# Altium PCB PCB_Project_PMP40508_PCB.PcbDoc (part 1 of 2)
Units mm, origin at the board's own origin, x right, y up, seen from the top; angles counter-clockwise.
Board outline 120 x 67 mm, 2 copper layers (Top Layer, Bottom Layer), stack 1.575 mm thick; 78 components, 43 nets, 177 pads, 0 vias.
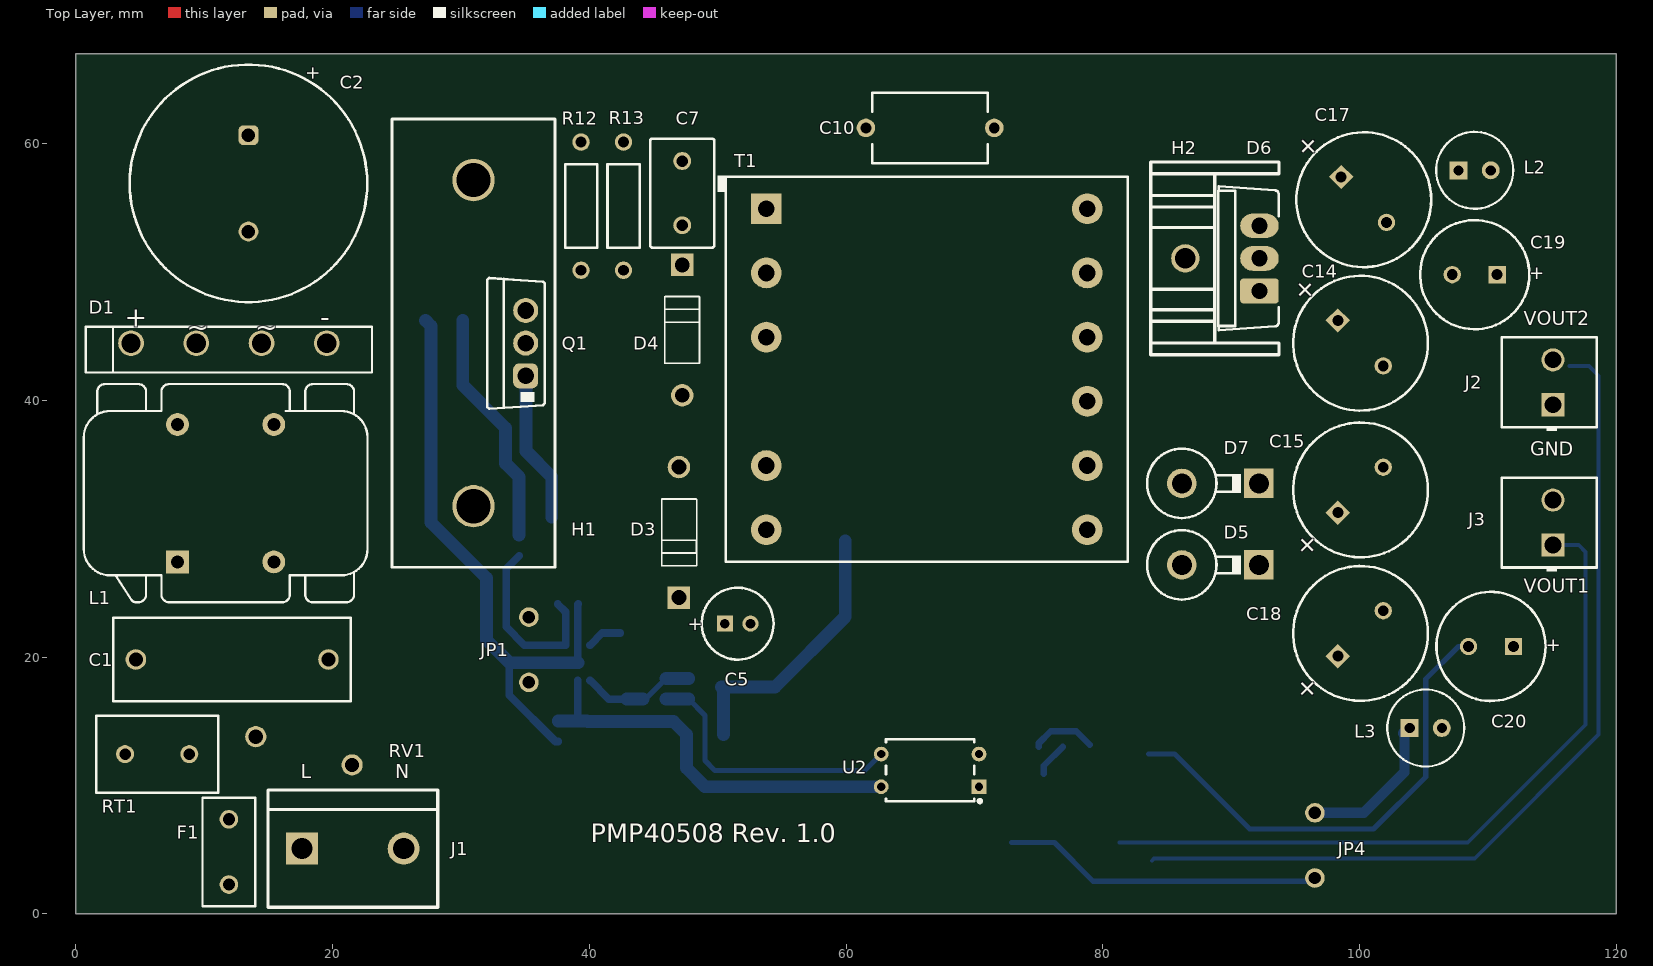
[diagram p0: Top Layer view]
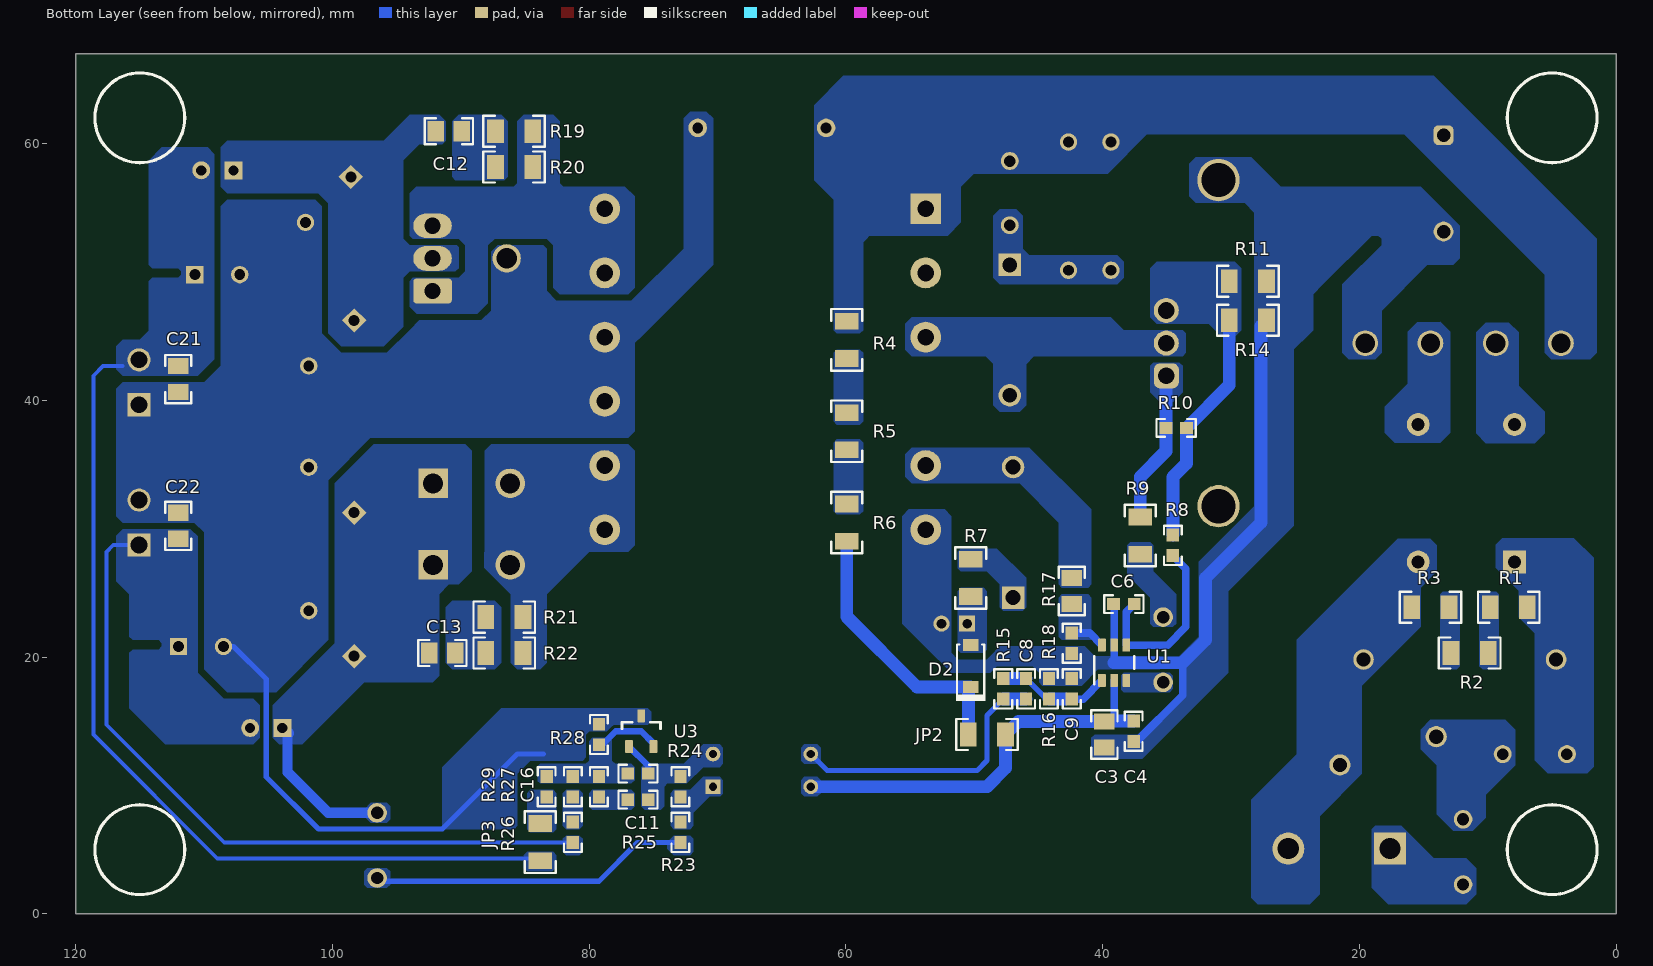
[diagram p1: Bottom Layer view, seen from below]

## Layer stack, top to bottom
Top Solder: solder mask 0.0102, Solder Resist, Dk 3.5
Top Layer: signal copper 0.0356
Dielectric1: core 1.5037, FR-4, Dk 4.8
Bottom Layer: signal copper 0.0356
Bottom Solder: solder mask 0.0102, Solder Resist, Dk 3.5

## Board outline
0,0 0,67 120,67 120,0

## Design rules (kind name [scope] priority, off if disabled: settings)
AcuteAngle [All] p1: minimum=4.50000000000000E+0001 checktracksonly=FALSE
AssemblyTestPointUsage [All] p1: valid=2
Clearance Clearance_BoardEdge_MountingHoles [OnCopper and InComponentClass('Mounting Holes') vs IsKeepOut] p1: gap=1.016 ignorepadtopadclearanceinfootprint=FALSE except(0: Arc-Hole Track-Hole SMDPad-Hole THPad-Hole Via-Hole Fill-Hole Poly-Hole Region-Hole Text-Hole)
Clearance Clearance_BoardEdge_Poly [OnCopper and InPoly vs IsKeepOut] p2: gap=0.635 ignorepadtopadclearanceinfootprint=FALSE except(0: Arc-Hole Track-Hole SMDPad-Hole THPad-Hole Via-Hole Fill-Hole Poly-Hole Region-Hole Text-Hole)
Clearance Clearance_BoardEdge [OnCopper and Not InComponentClass('Logo') and not InComponentClass('FiducialMark') and not InRegion(1000,500,4000,800) and Not IsKeepout vs IsKeepOut] p3: gap=0.2 ignorepadtopadclearanceinfootprint=FALSE
Clearance Clearance_Poly [InPolygon] p4: gap=0.254 ignorepadtopadclearanceinfootprint=FALSE
Clearance [All] p5: gap=0.2 ignorepadtopadclearanceinfootprint=FALSE
ComponentClearance ComponentClearance_Logo [All] p1: gap=0.254 collisioncheckmode=3 verticalgap=0.254 showdistances=TRUE
ComponentClearance ComponentClearance_ScrewToNut [(HasFootprint('NY PMS 440 0025 PH')) vs (HasFootprint('Keystone_1902C'))] p2: gap=0.127 collisioncheckmode=3 verticalgap=0.254 showdistances=FALSE
ComponentClearance ComponentClearance_MountingHoles [InComponentClass('Mounting Holes')] p3: gap=0.254 collisioncheckmode=3 verticalgap=2540 showdistances=FALSE
ComponentClearance ComponentClearance_SmallPassives [HasFootprint('0201*') or HasFootprint('0402*') or HasFootprint('0508') or HasFootprint('0603*') or HasFootprint('0612') or HasFootprint('0805*') or HasFootprint('0815*') or HasFootprint('0830*') or HasFootprint('1206*') or HasFootprint('1210*') or HasFootprint('1808*') or HasFootprint('1812*') or HasFootprint('1825*') or HasFootprint('2010*') or HasFootprint('2220*') or HasFootprint('2225*') or HasFootprint('2512*') or HasFootprint('2728*') or HasFootprint('3518*') vs HasFootprint('0201*') or HasFootprint('0402*') or HasFootprint('0508') or HasFootprint('0603*') or HasFootprint('0612') or HasFootprint('0805*') or HasFootprint('0815*') or HasFootprint('0830*') or HasFootprint('1206*') or HasFootprint('1210*') or HasFootprint('1808*') or HasFootprint('1812*') or HasFootprint('1825*') or HasFootprint('2010*') or HasFootprint('2220*') or HasFootprint('2225*') or HasFootprint('2512*') or HasFootprint('2728*') or HasFootprint('3518*')] p4: gap=0.254 collisioncheckmode=3 verticalgap=0.254 showdistances=FALSE
ComponentClearance ComponentClearance_THtoSMT [IsThruComponent vs IsSMTComponent] p5: gap=0.254 collisioncheckmode=3 verticalgap=2540 showdistances=FALSE
ComponentClearance ComponentClearance_THtoTH [IsThruComponent vs IsThruComponent] p6: gap=0.254 collisioncheckmode=3 verticalgap=2540 showdistances=FALSE
ComponentClearance [All] p7: gap=0.254 collisioncheckmode=3 verticalgap=0.254 showdistances=FALSE
DiffPairsRouting [All] p1: maxlimit=2.54 minlimit=0.254 mostfreqgap=0.254 toplayer_minwidth=0.381 toplayer_maxwidth=0.381 toplayer_prefwidth=0.381 bottomlayer_minwidth=0.381 bottomlayer_maxwidth=0.381 bottomlayer_prefwidth=0.381 maxuncoupledlength=25.4
FabricationTestPointUsage TestPointUsage [All] p1: valid=2 allowmultiple=FALSE
FabricationTestpoint Testpoint [All] p1: side=3 testpointundercomponent=TRUE minsize=1.016 maxsize=2.54 preferedsize=1.524 minholesize=0 maxholesize=1.016 preferedholesize=0.813 testpointgrid=0.025 allowsidetop=TRUE allowsidebottom=TRUE usegrid=TRUE gridtolerance=0
FanoutControl Fanout_LCC [IsLCC] p1: bgadir=Out bgaviamode=Centered fanoutstyle=Auto fanoutdirection=Alternating viagrid=0.025 // Fanout_LCC (Default Rule)
FanoutControl Fanout_BGA [IsBGA] p2: bgadir=Out bgaviamode=Centered fanoutstyle=Auto fanoutdirection=Alternating viagrid=0.025 // Fanout_BGA (Default Rule)
FanoutControl Fanout_Default [All] p4: bgadir=Out bgaviamode=Centered fanoutstyle=Auto fanoutdirection=Alternating viagrid=0.025 // Fanout_Default (Default Rule)
FanoutControl Fanout_Small [(CompPinCount < 5)] p5: bgadir=Out bgaviamode=Centered fanoutstyle=Auto fanoutdirection=OutThenIn viagrid=0.025 // Fanout_Small (Default Rule)
Height [All] p1: minheight=0 maxheight=40 prefheight=12.7
HoleSize [All] p1: absolutevalues=TRUE maxlimit=6.375 minlimit=0.152 maxpercent=80.000 minpercent=20.000
MinimumAnnularRing [All] p1: minimumring=0.1
MinimumSolderMaskSliver MinimumSolderMaskSliver_Logo [InComponentClass('Logo') vs InComponentClass('Logo')] p1: minsoldermaskwidth=0.018
MinimumSolderMaskSliver [All] p2: minsoldermaskwidth=0
PlaneConnect [All] p1: planeconnectstyle=Direct reliefexpansion=0.254 reliefentries=4 reliefconductorwidth=0.254 reliefairgap=0.254
PolygonConnect [All] p1: connectstyle=Direct reliefconductorwidth=0.254 reliefentries=4 polygonreliefangle="90 Angle" airgapwidth=0.254
RoutingCorners [All] p1: cornerstyle=45-Degree minsetback=0.254 maxsetback=2.54
RoutingVias [All] p1: holewidth=0.406 width=0.864 viastyle="Through Hole" minholewidth=0.203 minwidth=0.406 maxholewidth=1.016 maxwidth=1.651
SMDToCorner [All] p1: distance=0
SilkToBoardRegionClearance [Not ((IsComment or IsDesignator) And (Hide <> 'False')) and not InRegion(1000,500,4000,800)] p1:
SilkToSilkClearance [All] p1: silktosilkclearance=0
SilkToSolderMaskClearance SilkscreenOverComponentPads [IsPad] p1: minsilkscreentomaskgap=0 clearancetoexposedcopper=TRUE
SolderMaskExpansion [All] p1: expansion=0.076
Width [All] p1: maxlimit=2.54 minlimit=0.152 preferedwidth=0.254 checkconnectedcopper=TRUE
13 further rules are at their usual default settings.

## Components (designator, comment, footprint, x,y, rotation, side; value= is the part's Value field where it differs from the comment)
C1 "890324025027CS" WCAP-FTX2_1800x600x1150 12.192,19.812 r180 top value=0.22uF
C2 "EKXG401ELL101MMN3S" Chemi-Con_1800x3150 13.462,56.896 r270 top value=100uF
C3 "C2012X7R1H225K125AC" 0805_HV 39.878,13.97 r270 bottom value=2.2uF
C4 "GRM188R71H103KA01D" 0603 37.592,14.224 r270 bottom value=0.01uF
C5 "EKMG350ELL470ME11D" Chemi-Con_500x1100 51.562,22.606 r0 top value=47uF
C6 "CL10B101KB8NNNC" 0603 38.354,24.13 r0 bottom value=100pF
C7 "CK45-B3AD222KYNNA" CK45_850x500x1250 47.244,56.134 r270 top value=2200pF
C8 "GRM188R71H682KA01D" 0603 45.974,17.526 r90 bottom value=6800pF
C9 "GRM188R71H222KA01D" 0603 42.418,17.526 r90 bottom value=2200pF
C10 "C921U222MVVDBA7317" C900_9x13 66.548,61.214 r180 top value=2200pF
C11 "GRM188R71H223KA01D" 0603 76.2,10.922 r180 bottom value=0.022uF
C12 "GRM21A5C2E101JW01D" 0805_HV 90.932,60.96 r180 bottom value=100pF
C13 "GRM21A5C2E101JW01D" 0805_HV 91.44,20.32 r180 bottom value=100pF
C14 "EKZE250ELL681MJ20S" Chemi-Con_1000x2000 100.076,44.45 r315 top value=680uF
C15 "EKZE100ELL102MJ16S" Chemi-Con_1000x1600 100.076,33.02 r45 top value=1000uF
C16 "GRM188R71E224KA88D" 0603 79.248,9.906 r270 bottom value=0.22uF
C17 "EKZE250ELL681MJ20S" Chemi-Con_1000x2000 100.33,55.626 r315 top value=680uF
C18 "EKZE100ELL102MJ16S" Chemi-Con_1000x1600 100.076,21.844 r45 top value=1000uF
C19 "EKZE250ELL221MHB5D" Chemi-Con_800x1150 108.966,49.784 r180 top value=220uF
C20 "EKZE100ELL471MHB5D" Chemi-Con_800x1150 110.236,20.828 r180 top value=470uF
C21 "GRM216R61E105KA12D" 0805_HV 112.014,41.656 r270 bottom value=1uF
C22 "GRM216R61E105KA12D" 0805_HV 112.014,30.226 r90 bottom value=1uF
D1 "GBU4J-BP" GBU 11.938,44.45 r0 top value=600V
D2 "1N4148WFL-G3-08" SOD-123FL 50.292,19.304 r90 bottom value=100V
D3 "UF4007-TP" DO-41 46.99,29.718 r90 top value=1000V
D4 "UF4007-TP" DO-41 47.244,45.466 r270 top value=1000V
D5 "SB540" DO-201AD_Vert 89.154,27.178 r180 top
D6 "MBRF20L120CT" TO-220AB 92.202,51.054 r90 top
D7 "SB540" DO-201AD_Vert 89.154,33.528 r180 top
F1 "RST 2.5-BULK" FUSE_RST 11.938,4.826 r270 top
H1 "531102B02500G" 531102 30.988,44.45 r90 top locked
H2 "" PCBComponent_1#1 93.726,51.054 r90 top
J1 "1-1318301-2" Amp_1-1318301-2 21.59,5.08 r0 top
J2 "691214110002" Wurth_691214110002 115.062,41.402 r90 top
J3 "691214110002" Wurth_691214110002 115.062,30.48 r90 top
JP1 "923345-02-C" 923345-02-C 35.306,20.574 r90 top
JP2 "RC1206JR-070RL" 1206 49.022,13.97 r0 bottom value=0
JP3 "RC1206JR-070RL" 1206 83.82,5.588 r270 bottom value=0
JP4 "923345-02-C" 923345-02-C 96.52,5.334 r90 top
L1 "744823220" WE-CMB_M 11.684,32.766 r90 top value=20mH
L2 "7447462022" WE-TI_5075 108.966,57.912 r0 top value=2.2uH
L3 "7447462022" WE-TI_5075 105.156,14.478 r0 top value=2.2uH
Q1 "IPA65R400CEXKSA1" TO-220FP 35.052,44.45 r90 top locked
R1 "RC1206FR-071M5L" 1206 8.382,23.876 r0 bottom value=1.50Meg
R2 "RC1206FR-071M5L" 1206 11.43,20.32 r0 bottom value=1.50Meg
R3 "RC1206FR-071M5L" 1206 14.478,23.876 r0 bottom value=1.50Meg
R4 "CRCW12063M30JNEA" 1206 59.944,44.704 r90 bottom value=3.3Meg
R5 "CRCW12063M30JNEA" 1206 59.944,37.592 r90 bottom value=3.3Meg
R6 "CRCW12063M30JNEA" 1206 59.944,30.48 r90 bottom value=3.3Meg
R7 "RC1206FR-078R2L" 1206 50.292,26.162 r90 bottom value=8.20
R8 "RC0603FR-071KL" 0603 34.544,28.702 r90 bottom value=1.00k
R9 "RC1206FR-0710RL" 1206 37.084,29.464 r90 bottom value=10.0
R10 "RC0603FR-0710KL" 0603 34.29,37.846 r0 bottom value=10.0k
R11 "ERJ-8RQFR56V" 1206 28.702,49.276 r0 bottom value=0.56
R12 "PR01000101503JR500" PR01 39.37,55.118 r270 top value=150k
R13 "PR01000101503JR500" PR01 42.672,55.118 r270 top value=150k
R14 "ERJ-8RQFR56V" 1206 28.702,46.228 r0 bottom value=0.56
R15 "RC0603FR-0732K4L" 0603 47.752,17.526 r270 bottom value=32.4k
R16 "RC0603FR-074K02L" 0603 44.196,17.526 r270 bottom value=4.02k
R17 "ERJ-6ENF7502V" 0805_HV 42.418,25.146 r90 bottom value=75.0k
R18 "RC0603FR-0718KL" 0603 42.418,21.082 r90 bottom value=18.0k
R19 "CRCW120630R0JNEA" 1206 85.852,60.96 r0 bottom value=30
R20 "CRCW120630R0JNEA" 1206 85.852,58.166 r0 bottom value=30
R21 "CRCW120630R0JNEA" 1206 86.614,23.114 r0 bottom value=30
R22 "CRCW120630R0JNEA" 1206 86.614,20.32 r0 bottom value=30
R23 "RC0603FR-07470RL" 0603 72.898,6.35 r270 bottom value=470
R24 "RC0603FR-071KL" 0603 72.898,9.906 r270 bottom value=1.00k
R25 "RC0603FR-07470RL" 0603 76.2,8.89 r180 bottom value=470
R26 "RC0603FR-0720RL" 0603 81.28,6.35 r270 bottom value=20.0
R27 "RC0603FR-0742K2L" 0603 81.28,9.906 r270 bottom value=42.2k
R28 "RC0603FR-0742K2L" 0603 79.248,13.97 r270 bottom value=42.2k
R29 "RC0603FR-071ML" 0603 83.312,9.906 r270 bottom value=1.00Meg
RT1 "B57235S0509M000" S235 6.35,12.446 r180 top value=5.0
RV1 "B72210S2271K101" TDK_B72210S2271K101 17.78,12.7 r0 top value="430 V"
T1 "750344241" PCBComponent_1#2 66.294,42.418 r0 top locked value=236uH
U1 "UCC28742DBVR" DBV0006A_N 39.116,19.558 r90 bottom
U2 "FOD817A" DIP-4 66.548,11.176 r180 top
U3 "TL431LIAIDBZR" DBZ0003A_N 75.946,14.224 r90 bottom

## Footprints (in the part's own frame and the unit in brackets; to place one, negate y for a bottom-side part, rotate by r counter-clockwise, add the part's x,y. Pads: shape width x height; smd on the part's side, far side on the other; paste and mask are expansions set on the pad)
0603 [mm] "0603 from SM-752 data"
  rect 1x0.95 smd: 1(-0.8,0) 2(0.8,0)
  silkscreen extent -1.52,-0.69 1.52,0.69, body extent -0.87,-0.47 0.87,0.47, height 1
0805_HV [mil] "0805 with 30mil clearance between pads"
  rect 50x63 smd: 1(-40,0) 2(40,0)
  silkscreen extent -74,-40 74,40, body extent -43,-29 43,29, height 57
1206 [mm] "1206 from SM-752 data"
  rect 1.3x1.85 smd: 1(-1.45,0) 2(1.45,0)
  silkscreen extent -2.4,-1.21 2.4,1.21, body extent -1.7,-0.9 1.7,0.9, height 1.35
531102 [mm] "TH, 2-Leads, Body 34.92x12.7mm, Pin Spacing 25.4mm"
  round 3.3 hole 2.67: 1(-12.7,0) 2(12.7,0)
  silkscreen extent -17.46,-6.35 17.46,6.35, body extent -17.46,-6.36 17.46,6.36, height 38.1
923345-02-C [mil] "Wire Jumper"
  round 60 hole 38: 1(-100,0) 2(100,0)
  body extent -113,-37 113,40, height 100
Amp_1-1318301-2 [mm] "Amp recommended land pattern"
  rrect4% 2.5x2.5 hole 1.65: 1(-3.96,0)
  round 2.5 hole 1.65: 2(3.96,0)
  silkscreen extent -6.6,-4.57 6.6,4.57, body extent -5.91,-4.28 5.91,4.22, height 10.7
C900_9x13 [mm] "Kemet"
  round 1.45 hole 0.85: 1(-5,0) 2(5,0)
  silkscreen extent -4.5,-2.75 4.5,2.75, body extent -4.49,-2.75 4.49,2.75, height 12.96
Chemi-Con_500x1100 [mm] "TH, 2-Leads, Dia 5mm, Lead Sapcing 2mm"
  rect 1.25x1.25 hole 0.75: 1(-1,0)
  round 1.25 hole 0.75: 2(1,0)
  silkscreen extent -2.8,-2.8 2.8,2.8, body extent -2.75,-2.75 2.75,2.75, height 12.5
Chemi-Con_800x1150 [mm] "TH, 2-Leads, Dia 8mm"
  rect 1.35x1.35 hole 0.85: 1(-1.75,0)
  round 1.35 hole 0.85: 2(1.75,0)
  silkscreen extent -4.25,-4.25 4.25,4.25, body extent -4.22,-4.24 4.24,4.24, height 13.01
Chemi-Con_1000x1600 [mm] "TH, 2-Leads, Dia 10mm, Pin Spacing 5mm"
  rect 1.35x1.35 hole 0.85: 1(-2.5,0)
  round 1.35 hole 0.85: 2(2.5,0)
  silkscreen extent -5.25,-5.25 5.25,5.25, body extent -5.25,-5.25 5.26,5.25, height 17.5
Chemi-Con_1000x2000 [mm] "TH, 2-Leads, Body 10x20mm, Pin Spacing 5mm"
  rect 1.35x1.35 hole 0.85: 1(-2.5,0)
  round 1.35 hole 0.85: 2(2.5,0)
  silkscreen extent -5.25,-5.25 5.25,5.25, body extent -5.25,-5.25 5.25,5.25, height 21.5
Chemi-Con_1800x3150 [mm] "TH, 2-Leads, Dia 18mm, Pin Spacing 7.5mm"
  rrect50% 1.55x1.55 hole 1.05: 1(-3.75,0)
  round 1.55 hole 1.05: 2(3.75,0)
  silkscreen extent -9.25,-9.25 9.25,9.25, body extent -9.25,-9.35 9.26,9.15, height 33.01
CK45_850x500x1250 [mm] "TH, 2-Leads, Dia 8.5mm, Pin Spacing 5mm"
  round 1.4 hole 0.9: 1(-2.5,0) 2(2.5,0)
  silkscreen extent -4.25,-2.5 4.25,2.5, body extent -4.25,-2.5 4.25,2.5, height 12.5
DBV0006A_N [mm] "SOT23, 6-Leads, Body 2.9x1.6mm, Pitch 0.95mm, Lead Span 2.8mm, IPC Medium Density"
  rrect17% 1x0.6 smd: 1(-1.375,0.95) 2(-1.375,0) 3(-1.375,-0.95) 4(1.375,-0.95) 5(1.375,0) 6(1.375,0.95)
  silkscreen extent -1.68,-1.55 0.5,1.55, body extent -1.42,-1.46 1.42,1.46, height 1.12
DBZ0003A_N [mm] "SOT23, 3-Leads, Body 2.9x1.3mm, Pitch 0.95mm, Lead Span 2.4mm, IPC Medium Density"
  rrect17% 1x0.6 smd: 1(-1.2,0.95) 2(-1.2,-0.95) 3(1.2,0)
  silkscreen extent 0.2,-1.5 0.7,1.5, body extent -1.26,-1.46 1.26,1.46, height 0.98
DIP-4 [mm] "DIP, 4-Leads, Body 6.86x4.83mm, Pitch 2.54mm"
  rect 1.15x1.15 hole 0.65: 1(-3.81,1.27)
  round 1.15 hole 0.65: 2(-3.81,-1.27) 3(3.81,-1.27) 4(3.81,1.27)
  silkscreen extent -4,-2.41 3.43,2.52, body extent -4.02,-2.41 4.02,2.41, height 5.59
DO-41 [mm] "diode"
  rect 1.75x1.75 hole 1.15: 1(-5.08,0)
  round 1.75 hole 1.15: 2(5.08,0)
  silkscreen extent -2.62,-1.37 2.59,1.35, body extent -5.51,-1.36 5.51,1.36, height 2.72
DO-201AD_Vert [mm] "DO-201AD VERTICAL FOOTPRINT"
  rect 2.3x2.3 hole 1.55: 1(-3,0)
  round 2.3 hole 1.55: 2(3,0)
  silkscreen extent -1.6,-2.7 5.7,2.7, body extent -3.66,-2.65 5.66,2.66, height 14.8
FUSE_RST [mm] "Bel Fuse RST series May2012D"
  round 1.45 hole 0.95: 1(-2.54,0) 2(2.54,0)
  silkscreen extent -4.23,-2.05 4.23,2.05, body extent -4.22,-2.05 4.23,2.05, height 7.9
GBU [mm] "Comchip / Diodes Inc diode bridge"
  round 2 hole 1.5: 1(-7.62,0) 2(-2.54,0) 3(2.54,0) 4(7.62,0)
  silkscreen extent -11.15,-2.28 11.15,1.28, body extent -11.15,-2.28 11.15,1.28, height 21.55
PCBComponent_1#1 [mm]
  round 2.2 hole 1.6: 1(0,7.3)
  silkscreen extent -7.5,0 7.5,10, body extent -7.5,0 7.5,10, height 20
PCBComponent_1#2 [mm]
  rect 2.4x2.4 hole 1.3: 1(-12.5,12.5)
  round 2.4 hole 1.3: 2(-12.5,7.5) 3(-12.5,2.5) 5(-12.5,-7.5) 6(-12.5,-12.5) 7(12.5,-12.5) 8(12.5,-7.5) 9(12.5,-2.5) 10(12.5,2.5) 11(12.5,7.5) 12(12.5,12.5)
  silkscreen extent -16.3,-15 15.65,15.1, body extent -15.6,-15 15.6,15, height 16.05
PR01 [mm] "TH, 2-Leads, Axial, Dia 2.5mm, Pin Spacing 9.98mm"
  round 1.35 hole 0.85: 1(-4.99,0) 2(4.99,0)
  silkscreen extent -3.25,-1.25 3.25,1.25, body extent -5.28,-1.25 5.28,1.25, height 2.52
S235 [mm] "TH, 2-Leads, Dia 9.5mm, Pin Spacing 5mm"
  round 1.4 hole 0.9: 1(-2.5,0) 2(2.5,0)
  silkscreen extent -4.75,-3 4.75,3, body extent -4.75,-3 4.71,3, height 13.99
SOD-123FL [mm] "Copied from SOD-123"
  rect 0.915x1.22 smd: 1(-1.637,0) 2(1.637,0)
  silkscreen extent -2.74,-1.16 1.68,1.16, body extent -1.9,-0.9 1.9,0.9, height 1
TDK_B72210S2271K101 [mm] "TDK disc varistor"
  round 1.65 hole 1.1: 1(-3.75,1.1) 2(3.75,-1.1)
  body extent -6,-2.58 6,2.82, height 14.5
TO-220AB [mm] "Copied from Altium's version of TO3B"
  rrect25% 1.93x3 hole 1.27: 1(-2.54,0)
  oval 1.93x3 hole 1.27: 2(0,0) 3(2.54,0)
  silkscreen extent -5.61,-1.49 5.61,3.2, body extent -5.61,-1.49 5.61,3.2, height 19.42
TO-220FP [mm] "FM, Body 10.4x4.6mm, Pitch 2.55mm"
  rrect50% 1.95x1.95 hole 1.3: 1(-2.55,0)
  round 1.95 hole 1.3: 2(0,0) 3(2.55,0)
  silkscreen extent -5.1,-1.5 5.08,3, body extent -5.09,-1.5 5.09,3, height 19.41
WCAP-FTX2_1800x600x1150 [mm] "TH, 2-Leads, Body 18x6mm, Lead Spacing 15mm"
  round 1.6 hole 1.1: 1(-7.5,0) 2(7.5,0)
  silkscreen extent -9.25,-3.25 9.25,3.25, body extent -9.25,-3.25 9.25,3.25, height 12
WE-CMB_M [mil] "Wurth"
  rect 70x70 hole 40: 1(-210.63,147.64)
  round 70 hole 40: 2(-210.63,-147.64) 3(210.63,-147.64) 4(210.63,147.64)
  silkscreen extent -335,-435 335,435, body extent -335,-394 335,394, height 1044
WE-TI_5075 [mm] "Wurth WE-TI 5075"
  rect 1.4x1.4 hole 0.787: 1(-1.25,0)
  round 1.4 hole 0.787: 2(1.25,0)
  silkscreen extent -3,-3 3,3, body extent -3,-3 3,3, height 8.5
Wurth_691214110002 [mm] "Receptacle, 3.5mm, 2x1, TH"
  rect 1.8x1.8 hole 1.3: 1(-1.75,0)
  round 1.8 hole 1.3: 2(1.75,0)
  silkscreen extent -3.8,-3.4 3.5,4, body extent -3.9,-3.4 3.5,4, height 8.5

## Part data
C1: library part CMP-0012315-3, "CAP, Film, 0.22 uF, 275 V, +/- 10%, TH", Cap_Case=18x11.5x6mm, Manufacturer="Wurth Elektronik", Supplier Part Number 1=732-5802-ND, Tolerance_%=10%, Value1=Unknown, Value2=275V, ValueDisplayed=0.22uF
C2: library part CMP-0074694-1, "CAP, AL, 100 µF, 400 V, +/- 20%, TH", Cap_Case=18x31.5, Manufacturer=Chemi-Con, Supplier Part Number 1=565-1469-ND, Tolerance_%=20%, Value2=400V, ValueDisplayed=100µF
C3: library part CMP-0007877-2, "CAP, CERM, 2.2 uF, 50 V, +/- 10%, X7R, 0805", Cap_Case=0805, Manufacturer=TDK, Supplier Part Number 1=445-5968-1-ND, TempCo=X7R, Tolerance_%=10%, Value1="0.00366 ohm", Value2=50V, ValueDisplayed=2.2uF
C4: library part CMP-0007433-4, "CAP, CERM, 0.01 uF, 50 V, +/- 10%, X7R, 0603", Cap_Case=0603, Manufacturer=MuRata, Supplier Part Number 1=490-1512-1-ND, TempCo=X7R, Tolerance_%=10%, Value1=Unknown, Value2=50V, ValueDisplayed=0.01uF
C5: library part CMP-0010368-2, "CAP, AL, 47 uF, 35 V, +/- 20%, TH", Cap_Case=5x11mm, Manufacturer=Chemi-Con, Supplier Part Number 1=565-1320-ND, Tolerance_%=20%, Value1=Unknown, Value2=35V, ValueDisplayed=47uF
C6: library part CMP-0083857-1, "CAP, CERM, 100 pF, 50 V,+/- 10%, X7R, 0603", Cap_Case=0603, Manufacturer="Samsung Electro-Mechanics", TempCo=X7R, Tolerance_%=10%, Value2=50V, ValueDisplayed=100pF
C7: library part CMP-0009598-2, "CAP, CERM, 2200 pF, 1000 V, +/- 10%, B, D8.5xT5mm", Cap_Case=8.5x5x12.5mm, Manufacturer=TDK, Supplier Part Number 1=445-16006-ND, TempCo=B, Tolerance_%=10%, Value1=Unknown, Value2=1000V, ValueDisplayed=2200pF
C8: library part CMP-0007462-4, "CAP, CERM, 6800 pF, 50 V, +/- 10%, X7R, 0603", Cap_Case=0603, Manufacturer=MuRata, Supplier Part Number 1=490-1508-1-ND, TempCo=X7R, Tolerance_%=10%, Value1=Unknown, Value2=50V, ValueDisplayed=6800pF
C9: library part CMP-0007443-4, "CAP, CERM, 2200 pF, 50 V, +/- 10%, X7R, 0603", Cap_Case=0603, Manufacturer=MuRata, Supplier Part Number 1=490-1500-1-ND, TempCo=X7R, Tolerance_%=10%, Value1=Unknown, Value2=50V, ValueDisplayed=2200pF
C10: library part CMP-0078358-1, "CAP, CERM, 2200 pF, X1 400 VAC/Y1 400 VAC, +/- 20%, Y5V, D9xL13mm", Cap_Case=9x13mm, Manufacturer=Kemet, Supplier Part Number 1=399-9487-1-ND, TempCo=Y5V, Tolerance_%=20%, ValueDisplayed=2200pF
C11: library part CMP-0007444-4, "CAP, CERM, 0.022 uF, 50 V, +/- 10%, X7R, 0603", Cap_Case=0603, Manufacturer=MuRata, Supplier Part Number 1=490-1517-1-ND, TempCo=X7R, Tolerance_%=10%, Value1=Unknown, Value2=50V, ValueDisplayed=0.022uF
C12 C13: library part CMP-0008236-2, "CAP, CERM, 100 pF, 250 V, +/- 5%, C0G/NP0, 0805", Cap_Case=0805, Manufacturer=MuRata, Supplier Part Number 1=490-5542-1-ND, TempCo=C0G/NP0, Tolerance_%=5%, Value1=Unknown, Value2=250V, ValueDisplayed=100pF
C14 C17: library part CMP-0010412-1, "CAP, AL, 680 uF, 25 V, +/- 20%, TH", Cap_Case=10x20, Manufacturer=Chemi-Con, Supplier Part Number 1=565-1679-ND, Tolerance_%=20%, Value1=Unknown, Value2=25V, ValueDisplayed=680uF
C15 C18: library part CMP-0010377-1, "CAP, AL, 1000 uF, 10 V, +/- 20%, TH", Cap_Case=10x16mm, Manufacturer=Chemi-Con, Tolerance_%=20%, Value1=Unknown, Value2=10V, ValueDisplayed=1000uF
C16: library part CMP-0007415-4, "CAP, CERM, 0.22 uF, 25 V, +/- 10%, X7R, 0603", Cap_Case=0603, Manufacturer=MuRata, Supplier Part Number 1=490-3290-1-ND, TempCo=X7R, Tolerance_%=10%, Value1=Unknown, Value2=25V, ValueDisplayed=0.22uF
C19: library part CMP-0010404-1, "CAP, AL, 220 uF, 25 V, +/- 20%, TH", Cap_Case=8x11.5, Manufacturer=Chemi-Con, Supplier Part Number 1=565-1674-ND, Tolerance_%=20%, Value1=Unknown, Value2=25V, ValueDisplayed=220uF
C20: library part CMP-0010383-1, "CAP, AL, 470 uF, 10 V, +/- 20%, TH", Cap_Case=8x11.5, Manufacturer=Chemi-Con, Supplier Part Number 1=565-1647-ND, Tolerance_%=20%, Value1=Unknown, Value2=10V, ValueDisplayed=470uF
C21 C22: library part CMP-0008136-2, "CAP, CERM, 1 uF, 25 V, +/- 10%, X5R, 0805", Cap_Case=0805, Manufacturer=MuRata, Supplier Part Number 1=490-1700-1-ND, TempCo=X5R, Tolerance_%=10%, Value1="0.009 ohm", Value2=25V, ValueDisplayed=1uF
D1: library part CMP-0029241-3, "Diode, P-N-Bridge, 600 V, 4 A, TH", Manufacturer="Micro Commercial Components", Value1=4A, Value2=1V
D2: library part CMP-0076920-2, "Diode, Switching, 100 V, 0.15 A, SOD-123FL", Manufacturer=Vishay-Semiconductor, Value1=0.15A, Value2=1.2V
D3 D4: library part CMP-0077016-2, "Diode, Ultrafast, 1000 V, 1 A, TH", Manufacturer="Micro Commercial Components", Value1=1A, Value2=1.7V
D5 D7: library part CMP-0076935-2, "Diode, Schottky, 40 V, 5 A, TH", Average Rectified Current=5A, Forward Voltage=550mV, Manufacturer="ON Semiconductor / Fairchild", Max Forward Surge Current (Ifsm)=100A, Max Operating Temperature=150°C, Max Repetitive Reverse Voltage (Vrrm)=40V, Max Reverse Leakage Current=500uA, Max Surge Current=150A, Min Operating Temperature=-50°C, Package Quantity=1250, Supplier Part Number 1=SB540FSCT-ND
D6: library part CMP-0028764-3, "Diode, Schottky, 120 V, 20 A, TH", Manufacturer="Taiwan Semiconductor", Supplier Part Number 1=821-MBRF20L120CT
F1: library part CMP-0081660-1, "Fuse, 2.5 A, 250 VAC, TH", Irating_A=2.5A, Manufacturer="Bel Fuse", Supplier Part Number 1=507-1180-ND
H1: library part CMP-0004063-1, Manufacturer=Aavid, Supplier Part Number 1=HS352-ND
H2: library part HeatSink_2, Manufacturer=Aavid
J1: library part CMP-0054833-1, "Polarized Header, 7.92 mm, 2x1, Tin, TH", Color=Natural, Current_A=7.5A, Manufacturer="TE Connectivity", Supplier Part Number 1=A30521-ND, Voltage_V=250V
J2 J3: library part CMP-0054825-2, "Terminal Block, 3.5mm, 2x1, Tin, TH", Color=Green, Current_A=10A, Manufacturer="Wurth Elektronik", Supplier Part Number 1=732-2747-ND, Voltage_V=300V
JP1 JP4: library part CMP-0055439-1, "Jumper Wire, 200mil spacing, Red, pkg of 200", Manufacturer=3M, Supplier Part Number 1=923345-02-ND
JP2 JP3: library part CMP-0018759-2, "RES, 0, 5%, 0.25 W, 1206", Manufacturer="Yageo America", Power_W=250mW, Supplier Part Number 1=311-0.0ERCT-ND, TempCo="200 ppm/C", Tolerance_%=5%, Value2=0.25W, Value_Code=0000, ValueDisplayed=0
L1: library part CMP-0013122-2, "Coupled inductor, 20 mH, 1.5 A, 0.27 ohm, TH", Manufacturer="Wurth Elektronik", Supplier Part Number 1=732-1448-ND, ValueDisplayed=20mH
L2 L3: library part CMP-0064180-1, "Inductor, Unshielded Drum Core, Ferrite, 2.2 uH, 4.3 A, 0.01 ohm, TH", Manufacturer="Wurth Elektronik", Supplier Part Number 1=732-2566-ND, Value1="0.01 ohm", Value2=4.3A, ValueDisplayed=2.2uH
Q1: library part CMP-0001231-4, "MOSFET, N-CH, 650 V, 15.1 A, TO-220FP", Case/Package=TO-220-3, Input Capacitance=710pF, Manufacturer=Infineon, Max Dual Supply Voltage=650V, Max Operating Temperature=150°C, Max Power Dissipation=31W, Min Operating Temperature=-55°C, Supplier Part Number 1=726-IPA65R400CEXKSA1
R1 R2 R3: library part CMP-0018015-2, "RES, 1.50 M, 1%, 0.25 W, 1206", Manufacturer="Yageo America", Power_W=250mW, Supplier Part Number 1=311-1.50MFRCT-ND, TempCo="100 ppm/C", Tolerance_%=1%, Value2=0.25W, Value_Code=1M50, ValueDisplayed=1.50M
R4 R5 R6: library part CMP-0018673-3, "RES, 3.3 M, 5%, 0.25 W, AEC-Q200 Grade 0, 1206", Manufacturer=Vishay-Dale, Power_W=250mW, Supplier Part Number 1=541-3.3MECT-ND, TempCo="200 ppm/C", Tolerance_%=5%, Value2=0.25W, Value_Code=3M30, ValueDisplayed=3.3M
R7: library part CMP-0018523-2, "RES, 8.20, 1%, 0.25 W, 1206", Manufacturer="Yageo America", Power_W=250mW, Supplier Part Number 1=311-8.20FRCT-ND, TempCo="200 ppm/C", Tolerance_%=1%, Value2=0.25W, Value_Code=8R20, ValueDisplayed=8.20
R8 R24: library part CMP-0022895-5, "RES, 1.00 k, 1%, 0.1 W, 0603", Manufacturer=Yageo, Power_W=100mW, Supplier Part Number 1=311-1.00KHRCT-ND, TempCo="100 ppm/C", Tolerance_%=1%, Value2=0.1W, Value_Code=1k00, ValueDisplayed=1.00k
R9: library part CMP-0017851-2, "RES, 10.0, 1%, 0.25 W, 1206", Manufacturer="Yageo America", Power_W=250mW, Supplier Part Number 1=311-10.0FRCT-ND, TempCo="200 ppm/C", Tolerance_%=1%, Value2=0.25W, Value_Code=10R0, ValueDisplayed=10.0
R10: library part CMP-0022746-5, "RES, 10.0 k, 1%, 0.1 W, 0603", Manufacturer=Yageo, Power_W=100mW, Supplier Part Number 1=311-10.0KHRCT-ND, TempCo="100 ppm/C", Tolerance_%=1%, Value2=0.1W, Value_Code=10k0, ValueDisplayed=10.0k
R11 R14: library part CMP-0017792-3, "RES, 0.56, 1%, 0.25 W, AEC-Q200 Grade 0, 1206", Manufacturer=Panasonic, Power_W=250mW, Supplier Part Number 1=P.56RCT-ND, TempCo="250 ppm/C", Tolerance_%=1%, Value2=0.25W, Value_Code=R560, ValueDisplayed=0.56
R12 R13: library part CMP-0014328-2, "RES, 150 k, 5%, 1 W, AEC-Q200 Grade 0, D2.5xL6.5mm", Manufacturer=Vishay-Bccomponents, Power_W=1W, Supplier Part Number 1=PPC150KW-1TR-ND, TempCo="250 ppm/C", Tolerance_%=5%, Value_Code=150k
R15: library part CMP-0023030-5, "RES, 32.4 k, 1%, 0.1 W, 0603", Manufacturer=Yageo, Power_W=100mW, Supplier Part Number 1=311-32.4KHRCT-ND, TempCo="100 ppm/C", Tolerance_%=1%, Value2=0.1W, Value_Code=32k4, ValueDisplayed=32.4k
R16: library part CMP-0023144-5, "RES, 4.02 k, 1%, 0.1 W, 0603", Manufacturer=Yageo, Power_W=100mW, Supplier Part Number 1=311-4.02KHRCT-ND, TempCo="100 ppm/C", Tolerance_%=1%, Value2=0.1W, Value_Code=4k02, ValueDisplayed=4.02k
R17: library part CMP-0021786-3, "RES, 75.0 k, 1%, 0.125 W, AEC-Q200 Grade 0, 0805", Manufacturer=Panasonic, Power_W=125mW, Supplier Part Number 1=P75.0KCCT-ND, TempCo="100 ppm/C", Tolerance_%=1%, Value2=0.125W, Value_Code=75k0, ValueDisplayed=75.0k
R18: library part CMP-0022852-5, "RES, 18.0 k, 1%, 0.1 W, 0603", Manufacturer=Yageo, Power_W=100mW, Supplier Part Number 1=311-18.0KHRCT-ND, TempCo="100 ppm/C", Tolerance_%=1%, Value2=0.1W, Value_Code=18k0, ValueDisplayed=18.0k
R19 R20 R21 R22: library part CMP-0018655-3, "RES, 30, 5%, 0.25 W, AEC-Q200 Grade 0, 1206", Manufacturer=Vishay-Dale, Power_W=250mW, Supplier Part Number 1=541-30ECT-ND, TempCo="200 ppm/C", Tolerance_%=5%, Value2=0.25W, Value_Code=30R0, ValueDisplayed=30
R23 R25: library part CMP-0023129-5, "RES, 470, 1%, 0.1 W, 0603", Manufacturer=Yageo, Power_W=100mW, Supplier Part Number 1=311-470HRCT-ND, TempCo="100 ppm/C", Tolerance_%=1%, Value2=0.1W, Value_Code=470R, ValueDisplayed=470
R26: library part CMP-0022908-4, "RES, 20.0, 1%, 0.1 W, 0603", Manufacturer=Yageo, Power_W=100mW, Supplier Part Number 1=311-20.0HRCT-ND, TempCo="100 ppm/C", Tolerance_%=1%, Value2=0.1W, Value_Code=20R0, ValueDisplayed=20.0
R27 R28: library part CMP-0023106-5, "RES, 42.2 k, 1%, 0.1 W, 0603", Manufacturer=Yageo, Power_W=100mW, Supplier Part Number 1=311-42.2KHRCT-ND, TempCo="100 ppm/C", Tolerance_%=1%, Value2=0.1W, Value_Code=42k2, ValueDisplayed=42.2k
R29: library part CMP-0022899-4, "RES, 1.00 M, 1%, 0.1 W, 0603", Manufacturer=Yageo, Power_W=100mW, Supplier Part Number 1=311-1.00MHRCT-ND, TempCo="100 ppm/C", Tolerance_%=1%, Value2=0.1W, Value_Code=1M00, ValueDisplayed=1.00M
RT1: library part CMP-0002553-2, "Thermistor NTC, 5.0 ohm, 20%, D9.5xT6mm", Case/Package=Radial, Manufacturer="TDK EPCOS", Max Operating Temperature=170°C, Min Operating Temperature=-55°C, Supplier Part Number 1=495-2093-ND, Tolerance_%=20%
RV1: library part CMP-0082388-2, "Varistor, 430V, 3.5kA, 10mm Disc, TH", Manufacturer=TDK
T1: library part RLTI-1168, "Transformer, 236 uH, TH", Manufacturer="Wurth Elektronik", ValueDisplayed=EER28
U1: library part CMP-0078369-2, "High-Efficiency Low-Cost Flyback Controller with Secondary-Side Regulation, DBV0006A (SOT-23-6)", Alternate Manufacturer="Texas Instruments"
U2: library part CMP-0006173-3, "Optocoupler, 5 kV, 80-160% CTR, TH", Manufacturer="Fairchild Semiconductor", Supplier Part Number 1=FOD817A-ND, Voltage_Isolation_Vrms=5kV
U3: library part CMP-0084729-1, "Programmable Shunt Regulator with Optimized Reference Current, DBZ0003A (SOT-23-3)", Alternate Manufacturer="Texas Instruments"

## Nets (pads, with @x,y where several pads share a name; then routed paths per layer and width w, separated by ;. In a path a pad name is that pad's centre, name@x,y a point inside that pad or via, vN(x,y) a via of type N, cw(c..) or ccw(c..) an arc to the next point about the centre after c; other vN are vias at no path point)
5V: C20.1 C22.1 J3.1 L3.2 R26.2 | length 56.3
  Bottom Layer w0.3: R26.2@81.28,5.55 108.42,5.55 117.602,14.732 117.602,28.194 117.066,28.73 J3.1@115.062,28.73
12V: C19.1 C21.1 J2.2 JP3.2 L2.2 | length 69.4
  Bottom Layer w0.3: JP3.2@83.82,4.138 84,4.318 108.966,4.318 118.618,13.97 118.618,41.91 117.856,42.672 116.332,42.672
GND: C2.2 C3.2 C4.2 C5.2 C6.2 C9.2 D1.4 H1.2 R11.1 R14.1 R16.1 R18.1 T1.6 U1.5 | length 47.1
  Bottom Layer w0.6: 33.782,19.558 33.782,17.018 37.376,13.424 C4.2@37.592,13.424 ; 39.116,19.558 U1.5@39.116,20.933 39.116,24.092 C6.2@39.154,24.13
  Bottom Layer w1: R14.1@27.252,46.228 27.686,45.794 27.686,30.48 32.004,26.162 32.004,21.336 33.782,19.558 39.116,19.558
"L Wire": F1.2 J1.1
"N Wire": C1.1 J1.2 L1.2 R3.2 RV1.2
NetC1_2: C1.2 L1.1 R1.1 RT1.2
NetC2_1: C2.1 C7.1 C10.2 D1.1 R4.2 R12.1 R13.1 T1.1
NetC5_1: C5.1 D2.2 R7.1
NetC6_1: C6.1 R8.1 U1.4 | length 14.6
  Bottom Layer w0.6: R8.1@34.544,27.902 33.528,26.886 33.528,22.352 34.947,20.933 U1.4@38.166,20.933 38.166,23.431 38.151,23.447 38.151,23.533 C6.1@37.554,24.13
NetC7_2: C7.2 D4.1 R12.2 R13.2
NetC8_1: C8.1 R15.2 U2.3 | length 21.6
  Bottom Layer w0.4: R15.2@47.752,16.726 49.022,15.456 49.022,11.938 49.784,11.176 61.468,11.176 U2.3@62.738,12.446
  Bottom Layer w1: C8.1@45.974,16.726 R15.2@47.752,16.726
NetC8_2: C8.2 C9.1 R15.1 R16.2 U1.1 | length 9
  Bottom Layer w0.4: R16.2@44.196,16.726 44.374,16.726 C8.2@45.974,18.326
  Bottom Layer w0.6: U1.1@40.066,18.183 41.523,16.726 42.926,16.726
  Bottom Layer w1: 42.926,16.726 R16.2@44.196,16.726 ; C8.2@45.974,18.326 R15.1@47.752,18.326
NetC11_1: C11.1 C16.1 R27.1 R28.2 R29.1 U3.2 | length 5.1
  Bottom Layer w0.5: U3.2@74.996,13.024 74.996,13.274 75.946,14.224 77.924,14.224 78.978,13.17 R28.2@78.994,13.17
NetC11_2: C11.2 R24.1 R25.2 U2.2 U3.1 | length 2.7
  Bottom Layer w0.5: C11.2@75.4,10.922 75.4,11.528 U3.1@76.896,13.024
NetC12_1: C12.1 C14.1 C17.1 D6.2 L2.1
NetC12_2: C12.2 R19.2 R20.2
NetC13_1: C13.1 C15.1 C18.1 D5.1 D7.1 JP4.2 L3.1 | length 11.9
  Bottom Layer w0.8: JP4.2@96.52,7.874 100.33,7.874 103.494,11.038 L3.1@103.494,14.066
  Bottom Layer w1: L3.1@103.494,14.066 L3.1@103.906,14.478
NetC13_2: C13.2 R21.2 R22.2
NetC16_2: C16.2 R25.1
NetD1_2: D1.2 L1.4
NetD1_3: D1.3 L1.3
NetD2_1: D2.1 JP2.2 R6.1 | length 21.6
  Bottom Layer w1: JP2.2@50.472,13.97 50.472,17.487 D2.1@50.292,17.667 54.469,17.667 59.944,23.141 R6.1@59.944,29.03
NetD3_1: D3.1 R7.2
NetD3_2: D3.2 R17.2 T1.5
NetD4_2: D4.2 Q1.2 T1.3
NetD5_2: D5.2 D7.2 R21.1 R22.1 T1.7 T1.8
NetD6_1: D6.1 D6.3 R19.1 R20.1 T1.11 T1.12
NetF1_1: F1.1 RT1.1 RV1.1
NetJP1_1: JP1.1 U1.3
NetJP1_2: JP1.2 R9.1
NetJP3_1: JP3.1 R29.2
NetJP4_1: JP4.1 R23.2 | length 25
  Bottom Layer w0.4: R23.2@72.898,5.55 76.238,5.55 79.248,2.54 96.266,2.54 JP4.1@96.52,2.794
NetQ1_1: Q1.1 R9.2 R10.2 | length 11.8
  Bottom Layer w1: Q1.1@35.052,41.9 35.09,41.862 R10.2@35.09,37.846 35.09,36.03 37.084,34.036 R9.2@37.084,30.914
NetQ1_3: Q1.3 R8.2 R10.1 R11.2 R14.2 | length 18.5
  Bottom Layer w1: R14.2@30.152,46.228 30.152,41.184 R10.1@33.49,37.846 33.49,35.09 34.544,34.036 R8.2@34.544,29.502
NetR1_2: R1.2 R2.1
NetR2_2: R2.2 R3.1
NetR4_1: R4.1 R5.2
NetR5_1: R5.1 R6.2
NetR23_1: R23.1 R24.2 U2.1
NetR26_1: R26.1 R27.2
SGND: C10.1 C14.2 C15.2 C17.2 C18.2 C19.2 C20.2 C21.2 C22.2 H2.1 J2.1 J3.2 R28.1 T1.9 T1.10 U3.3 | length 37.7
  Bottom Layer w0.4: 83.566,12.446 85.598,12.446 91.44,6.604 101.092,6.604 105.156,10.668 105.156,18.288 107.696,20.828 C20.2@108.486,20.828
VDD: C3.1 C4.1 JP2.1 U1.2 U2.4 | length 32.1
  Bottom Layer w0.6: 38.862,15.024 39.116,15.278 U1.2@39.116,18.183
  Bottom Layer w1: C4.1@37.592,15.024 38.862,15.024 39.84,15.024 C3.1@39.878,14.986 46.556,14.986 JP2.1@47.572,13.97 47.572,11.356 49.022,9.906 U2.4@62.738,9.906
VS: R17.1 R18.2 U1.6 | length 2.7
  Bottom Layer w0.6: U1.6@40.066,20.933 41.015,21.882 R18.2@42.418,21.882
pads on no net: H1.1 T1.2

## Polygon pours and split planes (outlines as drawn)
NetJP4_1 on Bottom Layer "BOTTOM_LAYER_NETJP4_1_P136" (solid, remove dead copper, pour order 136): 72.136,6.096 73.406,6.096 73.914,5.588 73.914,5.08 73.406,4.572 72.136,4.572 71.882,4.826 71.882,5.842
SGND on Bottom Layer "BOTTOM_LAYER_SGND_P134" (solid, remove dead copper, pour order 134): 83.824,11.942 84.578,11.942 85.598,10.922 85.598,6.858 85.852,6.604 91.44,6.604 91.44,11.43 86.868,16.002 83.82,16.002
NetJP4_1 on Bottom Layer "BOTTOM_LAYER_NETJP4_1_P132" (solid, remove dead copper, pour order 132): 97.282,2.032 95.758,2.032 95.504,2.286 95.504,3.302 95.758,3.556 97.282,3.556 97.536,3.302 97.536,2.286
NetC13_1 on Bottom Layer "BOTTOM_LAYER_NETC13_1_P130" (solid, remove dead copper, pour order 130): 95.758,8.636 97.028,8.636 97.536,8.128 97.536,7.62 97.028,7.112 95.758,7.112 95.504,7.366 95.504,8.382
5V on Bottom Layer "BOTTOM_LAYER_5V_P128" (solid, remove dead copper, pour order 128): 80.772,6.096 81.788,6.096 82.042,5.842 82.042,4.826 81.788,4.572 80.772,4.572 80.518,4.826 80.518,5.842
12V on Bottom Layer "BOTTOM_LAYER_12V_P082" (solid, remove dead copper, pour order 82): 82.804,4.826 82.55,4.572 82.55,3.616 82.864,3.302 84.836,3.302 85.09,3.556 85.09,4.572 84.836,4.826
NetJP3_1 on Bottom Layer "BOTTOM_LAYER_NETJP3_1_P078" (solid, remove dead copper, pour order 78): 82.55,9.398 82.804,9.652 84.582,9.652 84.836,9.398 84.836,6.604 84.582,6.35 82.804,6.35 82.55,6.604
NetR26_1 on Bottom Layer "BOTTOM_LAYER_NETR26_1_P076" (solid, remove dead copper, pour order 76): 80.772,9.652 80.518,9.398 80.518,6.858 80.772,6.604 81.788,6.604 82.042,6.858 82.042,9.398 81.788,9.652
NetC16_2 on Bottom Layer "BOTTOM_LAYER_NETC16_2_P074" (solid, remove dead copper, pour order 74): 76.454,9.398 76.708,9.652 79.756,9.652 80.01,9.398 80.01,8.382 79.756,8.128 76.708,8.128 76.454,8.382
SGND on Bottom Layer "BOTTOM_LAYER_SGND_P072" (solid, remove dead copper, pour order 72): 75.184,15.748 75.438,16.002 84.074,16.002 84.074,12.192 83.82,11.938 80.518,11.938 80.264,12.192 80.264,13.97 80.01,14.224 78.486,14.224 77.978,14.732 75.438,14.732 75.184,14.986
NetC11_1 on Bottom Layer "BOTTOM_LAYER_NETC11_1_P068" (solid, remove dead copper, pour order 68): 76.708,11.684 77.978,11.684 78.232,11.938 78.232,13.516 78.432,13.716 79.756,13.716 80.01,13.462 80.01,11.938 80.264,11.684 83.82,11.684 84.003,11.501 84.003,10.343 83.82,10.16 76.708,10.16 76.454,10.414 76.454,11.43
NetC11_2 on Bottom Layer "BOTTOM_LAYER_NETC11_2_P066" (solid, remove dead copper, pour order 66): 69.85,13.208 71.12,13.208 72.644,11.684 75.692,11.684 75.946,11.43 75.946,8.382 75.692,8.128 74.422,8.128 74.168,8.382 74.168,9.906 73.914,10.16 72.39,10.16 71.12,11.43 69.85,11.43 69.596,11.684 69.596,12.954
NetR23_1 on Bottom Layer "BOTTOM_LAYER_NETR23_1_P064" (solid, remove dead copper, pour order 64): 71.12,10.668 72.136,9.652 73.406,9.652 73.66,9.398 73.66,6.858 73.406,6.604 72.136,6.604 71.882,6.858 71.882,7.874 70.612,9.144 69.81,9.144 69.596,9.358 69.596,10.414 69.85,10.668
12V on Bottom Layer "BOTTOM_LAYER_12V_P062" (solid, remove dead copper, pour order 62): 110.49,41.91 109.22,43.18 109.22,59.182 109.728,59.69 113.284,59.69 114.3,58.674 114.3,45.41 115.006,44.704 116.332,44.704 116.84,44.196 116.84,42.418 116.332,41.91
5V on Bottom Layer "BOTTOM_LAYER_5V_P060" (solid, remove dead copper, pour order 60): 105.664,13.716 105.664,16.256 106.172,16.764 108.458,16.764 110.49,18.796 110.49,29.4 111.062,29.972 116.332,29.972 116.84,29.464 116.84,25.908 115.824,24.892 115.824,16.002 113.03,13.208 106.172,13.208
NetC13_1 on Bottom Layer "BOTTOM_LAYER_NETC13_1_P058" (solid, remove dead copper, pour order 58): 99.314,21.59 104.648,16.256 104.648,13.716 104.14,13.208 102.362,13.208 97.536,18.034 97.536,21.59
NetD5_2 on Bottom Layer "BOTTOM_LAYER_NETD5_2_P054" (solid, remove dead copper, pour order 54): 85.598,19.05 86.106,19.558 86.106,24.892 88.157,26.943 88.157,28.175 88.138,28.194 88.138,28.702 79.756,28.702 79.756,28.448 83.312,24.892 83.312,19.558 83.82,19.05
NetC13_1 on Bottom Layer "BOTTOM_LAYER_NETC13_1_P052" (solid, remove dead copper, pour order 52): 89.154,36.068 89.662,36.576 96.774,36.576 99.822,33.528 99.822,25.4 99.822,20.066 97.79,18.034 92.202,18.034 91.694,18.542 91.694,24.892 90.932,25.654 90.17,25.654 89.154,26.67
NetC13_2 on Bottom Layer "BOTTOM_LAYER_NETC13_2_P048" (solid, remove dead copper, pour order 48): 87.376,24.384 90.678,24.384 91.186,23.876 91.186,19.558 90.678,19.05 87.376,19.05 86.868,19.558 86.868,23.876
NetD5_2 on Bottom Layer "BOTTOM_LAYER_NETD5_2_P046" (solid, remove dead copper, pour order 46): 76.962,36.576 87.63,36.576 88.138,36.068 88.138,28.194 76.962,28.194 76.454,28.702 76.454,36.068
NetC12_1 on Bottom Layer "BOTTOM_LAYER_NETC12_1_P044" (solid, remove dead copper, pour order 44): 91.186,61.722 91.694,62.23 93.98,62.23 96.266,59.944 94.742,58.42 93.218,59.944 91.44,59.944 91.186,60.198
NetC12_2 on Bottom Layer "BOTTOM_LAYER_NETC12_2_P042" (solid, remove dead copper, pour order 42): 86.36,61.722 86.868,62.23 90.17,62.23 90.678,61.722 90.678,57.404 90.424,57.15 86.614,57.15 86.36,57.404
NetD6_1 on Bottom Layer "BOTTOM_LAYER_NETD6_1_P040" (solid, remove dead copper, pour order 40): 82.804,62.23 85.09,62.23 85.598,61.722 85.598,56.896 86.36,56.134 81.534,56.134 82.296,56.896 82.296,61.722
NetC12_1 on Bottom Layer "BOTTOM_LAYER_NETC12_1_P038" (solid, remove dead copper, pour order 38): 100.076,60.198 108.204,60.198 108.712,59.69 108.712,56.642 108.204,56.134 101.092,56.134 100.076,55.118
NetC12_1 on Bottom Layer "BOTTOM_LAYER_NETC12_1_P036" (solid, remove dead copper, pour order 36): 90.327,52.07 93.98,52.07 94.488,52.578 94.488,58.674 96.012,60.198 100.33,60.198 100.33,45.212 99.314,44.196 96.012,44.196 94.488,45.72 94.488,49.53 93.98,50.038 90.424,50.038 90.17,50.292 90.17,51.913
NetD6_1 on Bottom Layer "BOTTOM_LAYER_NETD6_1_P034" (solid, remove dead copper, pour order 34): 77.216,56.642 93.472,56.642 93.98,56.134 93.98,52.832 93.726,52.578 90.17,52.578 89.662,52.07 89.662,50.038 90.17,49.53 93.726,49.53 93.98,49.276 93.98,47.273 93.443,46.736 88.71,46.736 87.884,47.562 87.884,52.07 87.376,52.578 83.312,52.578 82.804,52.07 82.804,48.768 82.296,48.26 76.962,48.26 76.454,48.768 76.454,55.88
GND on Bottom Layer "BOTTOM_LAYER_GND_P032" (solid, remove dead copper, pour order 32): 32.766,58.928 33.274,58.42 33.274,55.88 32.766,55.372 28.956,55.372 28.194,54.61 27.686,54.61 26.162,56.134 25.908,56.388 28.448,58.928
GND on Bottom Layer "BOTTOM_LAYER_GND_P030" (solid, remove dead copper, pour order 30): 18.288,43.688 18.288,46.99 14.732,50.546 12.7,50.546 12.192,51.054 12.192,53.594 15.24,56.642 26.162,56.642 28.194,54.61 28.194,44.196 27.686,43.688 25.4,43.688 23.622,45.466 23.622,48.26 22.86,49.022 21.336,49.022 21.336,43.688 20.828,43.18 18.796,43.18
NetD4_2 on Bottom Layer "BOTTOM_LAYER_NETD4_2_P028" (solid, remove dead copper, pour order 28): 38.354,45.466 39.37,46.482 54.864,46.482 55.372,45.974 55.372,43.942 54.864,43.434 49.1,43.434 48.514,42.848 48.514,39.624 48.006,39.116 46.482,39.116 45.974,39.624 45.974,42.824 45.364,43.434 38.608,43.434 33.782,43.434 33.528,43.688 33.528,45.212 33.782,45.466
NetQ1_3 on Bottom Layer "BOTTOM_LAYER_NETQ1_3_P024" (solid, remove dead copper, pour order 24): 29.21,50.292 29.718,50.8 35.814,50.8 36.322,50.292 36.322,46.482 35.814,45.974 31.75,45.974 30.794,45.018 29.658,45.018 29.21,45.466
NetC7_2 on Bottom Layer "BOTTOM_LAYER_NETC7_2_P022" (solid, remove dead copper, pour order 22): 38.354,50.8 38.862,51.308 45.72,51.308 46.228,51.816 46.228,54.356 46.736,54.864 48.006,54.864 48.514,54.356 48.514,49.53 48.006,49.022 38.862,49.022 38.354,49.53
NetC2_1 on Bottom Layer "BOTTOM_LAYER_NETC2_1_P020" (solid, remove dead copper, pour order 20): 15.24,65.278 60.198,65.278 62.484,62.992 62.484,57.15 58.166,52.832 52.07,52.832 51.054,53.848 51.054,56.642 50.038,57.658 39.624,57.658 36.576,60.706 16.51,60.706 15.494,59.69 15.24,59.69
NetC2_1 on Bottom Layer "BOTTOM_LAYER_NETC2_1_P018" (solid, remove dead copper, pour order 18): 1.524,52.578 14.224,65.278 19.05,65.278 19.05,63.246 5.588,49.784 5.588,43.688 5.08,43.18 2.032,43.18 1.524,43.688
NetD1_3 on Bottom Layer "BOTTOM_LAYER_NETD1_3_P016" (solid, remove dead copper, pour order 16): 12.954,45.344 13.716,46.106 13.726,46.096 15.494,46.096 16.256,45.334 16.256,41.27 18.034,39.492 18.034,37.46 17.272,36.698 13.716,36.698 12.954,37.46
NetD1_2 on Bottom Layer "BOTTOM_LAYER_NETD1_2_P014" (solid, remove dead copper, pour order 14): 8.382,46.054 10.16,46.054 10.922,45.292 10.922,37.418 10.16,36.656 6.35,36.656 5.588,37.418 5.588,39.116 7.62,41.148 7.62,45.292
NetC1_2 on Bottom Layer "BOTTOM_LAYER_NETC1_2_P012" (solid, remove dead copper, pour order 12): 7.62,26.924 7.62,23.114 6.35,21.844 6.096,21.844 6.096,25.4
NetR2_2 on Bottom Layer "BOTTOM_LAYER_NETR2_2_P010" (solid, remove dead copper, pour order 10): 12.192,24.892 12.386,25.086 13.522,25.086 13.716,24.892 13.716,19.304 13.462,19.05 12.446,19.05 12.192,19.304
NetR1_2 on Bottom Layer "BOTTOM_LAYER_NETR1_2_P008" (solid, remove dead copper, pour order 8): 9.144,24.892 9.338,25.086 10.474,25.086 10.668,24.892 10.668,19.304 10.414,19.05 9.398,19.05 9.144,19.304
NetC1_2 on Bottom Layer "BOTTOM_LAYER_NETC1_2_P006" (solid, remove dead copper, pour order 6): 2.286,10.96 1.778,11.468 1.778,11.9 1.778,27.724 3.302,29.248 8.89,29.248 9.398,28.74 9.398,26.962 6.35,23.914 6.35,11.976 5.334,10.96
NetF1_1 on Bottom Layer "BOTTOM_LAYER_NETF1_1_P004" (solid, remove dead copper, pour order 4): 11.176,6.477 10.16,7.493 10.16,9.271 7.874,11.557 7.874,14.351 8.636,15.113 14.478,15.113 15.24,14.351 15.24,12.827 13.97,11.557 13.97,7.747 12.7,6.477
"N Wire" on Bottom Layer "BOTTOM_LAYER_N_WIRE_P002" (solid, remove dead copper, pour order 2): 19.812,11.684 19.812,17.78 15.24,22.352 15.24,25.4 13.97,26.67 13.97,28.702 14.478,29.21 17.018,29.21 24.892,21.336 24.892,11.684
"L Wire" on Bottom Layer "BOTTOM_LAYER_L_WIRE_P000" (solid, remove dead copper, pour order 0): 14.224,4.318 11.684,4.318 10.922,3.556 10.922,1.524 11.684,0.762 17.78,0.762 19.05,2.032 19.05,6.604 18.796,6.858 16.764,6.858
SGND on Bottom Layer "BOTTOM_LAYER_SGND_P084" (solid, remove dead copper, pour order 84): 76.962,47.752 82.55,47.752 83.312,48.514 83.312,51.816 83.566,52.07 87.122,52.07 87.63,51.562 87.63,46.99 88.392,46.228 93.218,46.228 93.98,45.466 95.758,43.688 99.314,43.688 100.838,45.212 100.838,55.118 101.346,55.626 108.204,55.626 108.712,55.118 108.712,36.83 108.458,37.084 76.962,37.084 76.454,37.592 76.454,47.244
SGND on Bottom Layer "BOTTOM_LAYER_SGND_P086" (solid, remove dead copper, pour order 86): 96.774,37.338 100.33,33.782 100.33,21.336 104.394,17.272 108.204,17.272 109.982,19.05 109.982,29.718 110.744,30.48 116.332,30.48 116.84,30.988 116.84,40.894 116.332,41.402 109.982,41.402 108.458,42.926 108.458,37.338
SGND on Bottom Layer "BOTTOM_LAYER_SGND_P088" (solid, remove dead copper, pour order 88): 70.866,62.484 70.358,61.976 70.358,50.546 75.692,45.212 76.708,44.196 76.962,44.196 76.962,47.752 76.708,47.752 72.644,51.816 72.644,61.976 72.136,62.484
VDD on Bottom Layer "BOTTOM_LAYER_VDD_P090" (solid, remove dead copper, pour order 90): 62.23,10.668 63.246,10.668 63.5,10.414 63.5,9.398 63.246,9.144 62.23,9.144 61.976,9.398 61.976,10.414
NetC8_1 on Bottom Layer "BOTTOM_LAYER_NETC8_1_P092" (solid, remove dead copper, pour order 92): 62.23,13.208 63.246,13.208 63.5,12.954 63.5,11.938 63.246,11.684 62.23,11.684 61.976,11.938 61.976,12.954
VS on Bottom Layer "BOTTOM_LAYER_VS_P094" (solid, remove dead copper, pour order 94): 41.148,24.892 40.894,24.638 40.894,21.336 43.18,21.336 43.434,21.59 43.434,24.638 43.18,24.892
NetD3_2 on Bottom Layer "BOTTOM_LAYER_NETD3_2_P096" (solid, remove dead copper, pour order 96): 54.864,36.322 55.372,35.814 55.372,34.036 54.864,33.528 46.482,33.528 43.434,30.48 43.434,25.654 43.18,25.4 41.148,25.4 40.894,25.654 40.894,31.496 45.72,36.322
NetJP1_1 on Bottom Layer "BOTTOM_LAYER_NETJP1_1_P098" (solid, remove dead copper, pour order 98): 38.354,18.796 38.608,18.542 38.608,17.526 38.354,17.272 34.798,17.272 34.544,17.526 34.544,18.542 34.798,18.796
NetC2_1 on Bottom Layer "BOTTOM_LAYER_NETC2_1_P100" (solid, remove dead copper, pour order 100): 58.674,45.466 58.674,52.324 57.912,53.086 60.96,56.134 60.96,52.578 60.96,45.466 60.706,45.212 58.928,45.212
NetR4_1 on Bottom Layer "BOTTOM_LAYER_NETR4_1_P102" (solid, remove dead copper, pour order 102): 58.928,43.942 60.706,43.942 60.96,43.688 60.96,38.354 60.706,38.1 58.928,38.1 58.674,38.354 58.674,43.688
NetR5_1 on Bottom Layer "BOTTOM_LAYER_NETR5_1_P104" (solid, remove dead copper, pour order 104): 58.928,36.957 60.706,36.957 60.96,36.703 60.96,31.369 60.706,31.115 58.928,31.115 58.674,31.369 58.674,36.703
NetC5_1 on Bottom Layer "BOTTOM_LAYER_NETC5_1_P106" (solid, remove dead copper, pour order 106): 49.276,25.4 49.022,25.146 49.022,20.574 49.276,20.32 51.054,20.32 51.308,20.574 51.308,25.146 51.054,25.4
NetD3_1 on Bottom Layer "BOTTOM_LAYER_NETD3_1_P108" (solid, remove dead copper, pour order 108): 45.974,26.162 48.26,28.448 51.054,28.448 51.308,28.194 51.308,26.924 51.054,26.67 49.022,26.67 48.006,25.654 48.006,23.876 47.752,23.622 46.228,23.622 45.974,23.876
GND on Bottom Layer "BOTTOM_LAYER_GND_P110" (solid, remove dead copper, pour order 110): 52.324,31.496 51.816,30.988 51.816,19.812 52.832,19.812 55.626,22.606 55.626,30.988 55.118,31.496
NetJP1_2 on Bottom Layer "BOTTOM_LAYER_NETJP1_2_P112" (solid, remove dead copper, pour order 112): 34.544,22.352 34.29,22.606 34.29,24.892 36.068,26.67 36.068,28.702 36.322,28.956 37.846,28.956 38.1,28.702 38.1,26.416 36.322,24.638 36.322,22.606 36.068,22.352
NetQ1_1 on Bottom Layer "BOTTOM_LAYER_NETQ1_1_P114" (solid, remove dead copper, pour order 114): 34.036,42.926 33.782,42.672 33.782,40.64 34.568,39.854 35.536,39.854 36.322,40.64 36.322,42.672 36.068,42.926
GND on Bottom Layer "BOTTOM_LAYER_GND_P116" (solid, remove dead copper, pour order 116): 35.56,20.066 40.64,20.066 41.402,20.828 48.006,20.828 48.768,20.066 48.768,19.304 45.466,19.304 44.958,18.796 44.958,18.034 44.704,17.78 41.656,17.78 40.386,19.05 35.56,19.05
GND on Bottom Layer "BOTTOM_LAYER_GND_P120" (solid, pour order 120): 48.26,20.574 49.022,19.812 51.308,19.812 51.816,20.32 53.34,20.32 51.816,18.796 48.768,18.796 48.26,19.304
"N Wire" on Bottom Layer "BOTTOM_LAYER_N_WIRE_P122" (solid, remove dead copper, pour order 122): 19.812,10.922 23.114,7.62 23.114,1.524 23.876,0.762 27.94,0.762 28.448,1.27 28.448,8.89 24.638,12.7 19.812,12.7
GND on Bottom Layer "BOTTOM_LAYER_GND_P124" (solid, remove dead copper, pour order 124): 25.146,44.196 25.146,30.226 30.48,24.892 32.512,24.892 32.512,27.432 28.194,31.75 28.194,44.196
GND on Bottom Layer "BOTTOM_LAYER_GND_P126" (solid, remove dead copper, pour order 126): 40.64,13.97 37.084,13.97 34.036,17.018 34.036,20.066 32.512,21.59 32.512,25.146 30.226,25.146 30.226,18.796 36.932,12.09 40.64,12.09 40.894,12.344 40.894,13.716

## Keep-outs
Keep-Out Layer:
  text ".Layer_Name" at 14.656,-21.806 h1.52

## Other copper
Top Layer:
  text ".Layer_Name" at 14.656,-21.806 h1.52
Bottom Layer:
  pour cut-out: 114.3,50.546 114.046,50.292 112.014,50.292 111.76,50.038 111.76,49.784 112.014,49.53 114.046,49.53 114.3,49.276
  pour cut-out: 115.824,21.59 115.57,21.336 113.538,21.336 113.284,21.082 113.284,20.828 113.538,20.574 115.57,20.574 115.824,20.32
  pour cut-out: 22.86,49.022 19.05,52.832 18.542,52.832 18.288,52.578 18.288,52.07 21.336,49.022
  text ".Layer_Name" at 14.656,-21.806 h1.52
